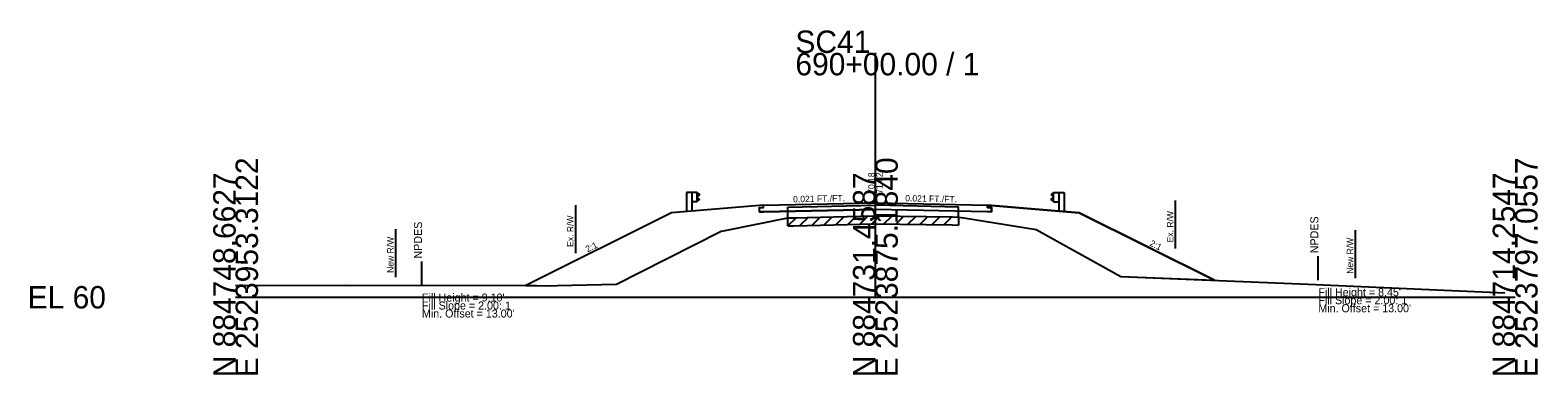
# Model space of a CAD drawing. Extents: x -26 to 183, y -10 to 24021.
# Drawn here: x -25.7 to 162.8, y 16990.3 to 17033.4 of the extents above; entities that cross this region are included whole.
import ezdxf

# ---------------------------------------------------------------- set-up
doc = ezdxf.new("R2010")
doc.units = 0
for name, color, linetype in [('RD_GPK_XS_Cell', 7, 'Continuous'), ('RD_XS_Base', 7, 'Continuous'), ('RD_XS_Buildup', 7, 'Continuous'), ('RD_XS_EarthShd', 7, 'Continuous'), ('RD_XS_EwShp', 7, 'Continuous'), ('RD_XS_ExGround', 7, 'Continuous'), ('RD_XS_ExPaveRet', 7, 'Continuous'), ('RD_XS_ExRW', 7, 'Continuous'), ('RD_XS_GR', 7, 'Continuous'), ('RD_XS_NewRW', 7, 'Continuous'), ('RD_XS_NPDES', 7, 'Continuous'), ('RD_XS_Pave', 7, 'Continuous'), ('RD_XS_TieSlope', 7, 'Continuous'), ('RD_XS_TX_Elev_EX', 7, 'Continuous'), ('RD_XS_TX_Elev_PR', 7, 'Continuous'), ('RD_XS_TX_Slope', 7, 'Continuous'), ('RD_XS_TX_Warning', 7, 'Continuous')]:
    doc.layers.add(name, color=color, linetype=linetype)

msp = doc.modelspace()

# ---------------------------------------------------------------- linework, layer by layer
at = {"layer": 'RD_GPK_XS_Cell'}
for p, q in [((80, 17000), (80, 17030.54)), ((0, 17000), (80, 17000)), ((80, 17000), (160, 17000))]:
    msp.add_line(p, q, dxfattribs=at)
at = {"layer": 'RD_XS_Base'}
for p in [(66.01, 17010.69), (93.99, 17010.69)]:
    msp.add_line(p, (80, 17010.98), dxfattribs=at)
at = {"layer": 'RD_XS_Buildup'}
for p, q in [((69.05, 17011.27), (80, 17011.5)), ((90.38, 17011.28), (80, 17011.5)), ((69.05, 17009.92), (69.05, 17011.27)), ((90.38, 17010.02), (90.38, 17011.28))]:
    msp.add_line(p, q, dxfattribs=at)
at = {"layer": 'RD_XS_EarthShd'}
for p, q in [((66, 17011.53), (58, 17010.86)), ((94, 17011.53), (102, 17010.86)), ((58, 17010.86), (54.5, 17010.57)), ((102, 17010.86), (105.5, 17010.57))]:
    msp.add_line(p, q, dxfattribs=at)
at = {"layer": 'RD_XS_EwShp'}
msp.add_lwpolyline([(40.26, 17001.46), (47.61, 17001.64), (50.57, 17003.13), (60.73, 17008.25), (61.21, 17008.35), (69.05, 17009.92), (69.8, 17009.94), (79.81, 17010.18), (89.64, 17010.04), (90.38, 17010.02), (91.07, 17009.91), (100.11, 17008.47), (110.71, 17002.6), (122.39, 17002.13), (105.5, 17010.57), (102, 17010.86), (94, 17011.53), (94, 17011.24), (94.5, 17011.23), (94.5, 17010.68), (93.99, 17010.69), (80, 17010.98), (66.01, 17010.69), (65.5, 17010.68), (65.5, 17011.23), (66, 17011.24), (66, 17011.53), (58, 17010.86), (54.5, 17010.57), (36.3, 17001.47), (37.61, 17001.47), (39.22, 17001.45)], close=True, dxfattribs=at)
msp.add_lwpolyline([(40.26, 17001.46), (47.61, 17001.64), (50.57, 17003.13), (60.73, 17008.25), (61.21, 17008.35), (69.05, 17009.92), (69.8, 17009.94), (79.81, 17010.18), (89.64, 17010.04), (90.38, 17010.02), (91.07, 17009.91), (100.11, 17008.47), (110.71, 17002.6), (122.39, 17002.13), (105.5, 17010.57), (102, 17010.86), (94, 17011.53), (94, 17011.24), (94.5, 17011.23), (94.5, 17010.68), (93.99, 17010.69), (80, 17010.98), (66.01, 17010.69), (65.5, 17010.68), (65.5, 17011.23), (66, 17011.24), (66, 17011.53), (58, 17010.86), (54.5, 17010.57), (36.3, 17001.47), (37.61, 17001.47), (39.22, 17001.45)], close=True, dxfattribs=at)
msp.add_lwpolyline([(40.26, 17001.46), (47.61, 17001.64), (50.57, 17003.13), (60.73, 17008.25), (61.21, 17008.35), (69.05, 17009.92), (69.8, 17009.94), (79.81, 17010.18), (89.64, 17010.04), (90.38, 17010.02), (91.07, 17009.91), (100.11, 17008.47), (110.71, 17002.6), (122.39, 17002.13), (105.5, 17010.57), (102, 17010.86), (94, 17011.53), (94, 17011.24), (94.5, 17011.23), (94.5, 17010.68), (93.99, 17010.69), (80, 17010.98), (66.01, 17010.69), (65.5, 17010.68), (65.5, 17011.23), (66, 17011.24), (66, 17011.53), (58, 17010.86), (54.5, 17010.57), (36.3, 17001.47), (37.61, 17001.47), (39.22, 17001.45)], close=True, dxfattribs=at)
msp.add_lwpolyline([(40.26, 17001.46), (47.61, 17001.64), (50.57, 17003.13), (60.73, 17008.25), (61.21, 17008.35), (69.05, 17009.92), (69.8, 17009.94), (79.81, 17010.18), (89.64, 17010.04), (90.38, 17010.02), (91.07, 17009.91), (100.11, 17008.47), (110.71, 17002.6), (122.39, 17002.13), (105.5, 17010.57), (102, 17010.86), (94, 17011.53), (94, 17011.24), (94.5, 17011.23), (94.5, 17010.68), (93.99, 17010.69), (80, 17010.98), (66.01, 17010.69), (65.5, 17010.68), (65.5, 17011.23), (66, 17011.24), (66, 17011.53), (58, 17010.86), (54.5, 17010.57), (36.3, 17001.47), (37.61, 17001.47), (39.22, 17001.45)], close=True, dxfattribs=at)
at = {"layer": 'RD_XS_ExGround'}
for p, q in [((61.21, 17008.35), (69.05, 17009.92)), ((69.05, 17009.92), (69.8, 17009.94)), ((69.8, 17009.94), (79.81, 17010.18)), ((79.81, 17010.18), (89.64, 17010.04)), ((89.64, 17010.04), (90.38, 17010.02)), ((90.38, 17010.02), (91.07, 17009.91)), ((91.07, 17009.91), (100.11, 17008.47)), ((50.57, 17003.13), (60.73, 17008.25)), ((60.73, 17008.25), (61.21, 17008.35)), ((100.11, 17008.47), (110.71, 17002.6)), ((47.61, 17001.64), (50.57, 17003.13)), ((110.71, 17002.6), (134.13, 17001.64)), ((0, 17001.47), (13.65, 17001.51)), ((13.65, 17001.51), (37.61, 17001.47)), ((37.61, 17001.47), (39.22, 17001.45)), ((39.22, 17001.45), (40.26, 17001.46)), ((40.26, 17001.46), (47.61, 17001.64)), ((134.13, 17001.64), (158.73, 17000.55))]:
    msp.add_line(p, q, dxfattribs=at)
at = {"layer": 'RD_XS_ExPaveRet'}
for p, q in [((69.05, 17008.92), (70.08, 17009.95)), ((69.05, 17008.92), (69.05, 17009.92)), ((70.55, 17008.96), (71.58, 17009.98)), ((72.05, 17008.99), (73.08, 17010.02)), ((73.55, 17009.03), (74.58, 17010.05)), ((75.05, 17009.07), (76.08, 17010.09)), ((76.55, 17009.1), (77.58, 17010.13)), ((78.05, 17009.14), (79.08, 17010.16)), ((79.55, 17009.17), (80.55, 17010.17)), ((81.05, 17009.16), (82.04, 17010.15)), ((82.55, 17009.14), (83.54, 17010.13)), ((84.05, 17009.12), (85.04, 17010.1)), ((85.55, 17009.1), (86.54, 17010.08)), ((87.05, 17009.07), (88.04, 17010.06)), ((88.55, 17009.05), (89.54, 17010.04)), ((90.38, 17010.02), (90.38, 17009.02)), ((69.05, 17008.92), (69.8, 17008.94)), ((69.8, 17008.94), (79.81, 17009.18)), ((79.81, 17009.18), (89.64, 17009.04)), ((89.64, 17009.04), (90.38, 17009.02))]:
    msp.add_line(p, q, dxfattribs=at)
at = {"layer": 'RD_XS_ExRW'}
for p, q in [((42.5, 17011.52), (42.5, 17005.52)), ((117.5, 17012.08), (117.5, 17006.08))]:
    msp.add_line(p, q, dxfattribs=at)
at = {"layer": 'RD_XS_GR'}
for p, q in [((56.4, 17013.11), (56.4, 17010.73)), ((57.06, 17013.11), (56.4, 17013.11)), ((57.06, 17013.11), (57.06, 17010.78)), ((57.73, 17013.11), (57.06, 17013.11)), ((57.73, 17011.95), (57.06, 17011.95)), ((57.73, 17011.95), (57.73, 17013.11)), ((57.73, 17013.04), (58, 17012.84)), ((58, 17012.79), (57.73, 17012.59)), ((58, 17012.27), (57.73, 17012.47)), ((57.73, 17012.02), (58, 17012.22)), ((58, 17012.84), (58, 17012.79)), ((58, 17012.22), (58, 17012.27)), ((102.27, 17013.04), (102, 17012.84)), ((102, 17012.84), (102, 17012.79)), ((102, 17012.79), (102.27, 17012.59)), ((102, 17012.27), (102.27, 17012.47)), ((102, 17012.22), (102, 17012.27)), ((102.27, 17012.02), (102, 17012.22)), ((102.27, 17013.11), (102.94, 17013.11)), ((102.27, 17011.95), (102.27, 17013.11)), ((102.27, 17011.95), (102.94, 17011.95)), ((102.94, 17013.11), (102.94, 17010.78)), ((102.94, 17013.11), (103.6, 17013.11)), ((103.6, 17013.11), (103.6, 17010.73))]:
    msp.add_line(p, q, dxfattribs=at)
at = {"layer": 'RD_XS_NewRW'}
for p, q in [((20, 17008.5), (20, 17002.5)), ((140, 17008.38), (140, 17002.38))]:
    msp.add_line(p, q, dxfattribs=at)
at = {"layer": 'RD_XS_NPDES'}
for p, q in [((23.3, 17001.47), (23.3, 17004.47)), ((135.39, 17002.13), (135.39, 17005.13))]:
    msp.add_line(p, q, dxfattribs=at)
at = {"layer": 'RD_XS_Pave'}
for p, q in [((66, 17011.53), (80, 17011.82)), ((66, 17011.24), (66, 17011.53)), ((80, 17011.82), (94, 17011.53)), ((94, 17011.24), (94, 17011.53)), ((65.5, 17011.23), (66, 17011.24)), ((65.5, 17010.68), (65.5, 17011.23)), ((65.5, 17010.68), (66.01, 17010.69)), ((94.5, 17010.68), (93.99, 17010.69)), ((94.5, 17011.23), (94, 17011.24)), ((94.5, 17010.68), (94.5, 17011.23))]:
    msp.add_line(p, q, dxfattribs=at)
at = {"layer": 'RD_XS_TieSlope'}
for p, q in [((54.5, 17010.57), (36.3, 17001.47)), ((105.5, 17010.57), (122.39, 17002.13))]:
    msp.add_line(p, q, dxfattribs=at)

# ---------------------------------------------------------------- texts
at = {"layer": 'RD_GPK_XS_Cell'}
for s, p in [('SC41', (70, 17030.54)), ('690+00.00 / 1', (70, 17027.74)), ('EL 60', (-26, 16998.6))]:
    msp.add_text(s, height=2.8, dxfattribs=at).set_placement(p)
for s, p in [('E 2523953.3122', (2.8, 16990)), ('E 2523875.1840', (82.8, 16990)), ('E 2523797.0557', (162.8, 16990)), ('N 884748.6627', (0, 16990)), ('N 884731.4587', (80, 16990)), ('N 884714.2547', (160, 16990))]:
    msp.add_text(s, height=2.8, rotation=90, dxfattribs=at).set_placement(p)
at = {"layer": 'RD_XS_ExRW'}
for p in [(42.25, 17006.3), (117.25, 17006.86)]:
    msp.add_text('Ex. R/W ', height=0.8, rotation=90, dxfattribs=at).set_placement(p)
at = {"layer": 'RD_XS_NewRW'}
for p in [(19.75, 17003.05), (139.75, 17002.93)]:
    msp.add_text('New R/W ', height=0.8, rotation=90, dxfattribs=at).set_placement(p)
at = {"layer": 'RD_XS_TX_Elev_EX'}
msp.add_text('70.18', height=0.8, rotation=90, dxfattribs=at).set_placement((79.9, 17012.93))
at = {"layer": 'RD_XS_TX_Elev_PR'}
msp.add_text('71.82', height=0.8, rotation=90, dxfattribs=at).set_placement((80.9, 17012.93))
at = {"layer": 'RD_XS_TX_Slope'}
for s, rotation, p in [('0.021 FT./FT.', 1.1916, (69.72, 17011.86)), ('0.021 FT./FT.', 358.8084, (83.73, 17011.99)), ('2:1', 26.5651, (44.01, 17005.6)), ('2:1', 333.4349, (114.22, 17006.49))]:
    msp.add_text(s, height=0.8, rotation=rotation, dxfattribs=at).set_placement(p)
at = {"layer": 'RD_XS_TX_Warning'}
for p in [(135.39, 17005.13), (23.3, 17004.47)]:
    msp.add_text(' NPDES', height=1, rotation=90, dxfattribs=at).set_placement(p)
for s, p in [("Fill Height = 9.10' ", (23.3, 16999.47)), ("Fill Height = 8.45' ", (135.39, 17000.13)), ('Fill Slope = 2.00: 1', (135.39, 16999.13)), ('Fill Slope = 2.00: 1', (23.3, 16998.47)), ("Min. Offset = 13.00' ", (23.3, 16997.47)), ("Min. Offset = 13.00' ", (135.39, 16998.13))]:
    msp.add_text(s, height=1, dxfattribs=at).set_placement(p)

doc.saveas('drawing.dxf')
